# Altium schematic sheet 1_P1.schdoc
size 426 x 300 mm
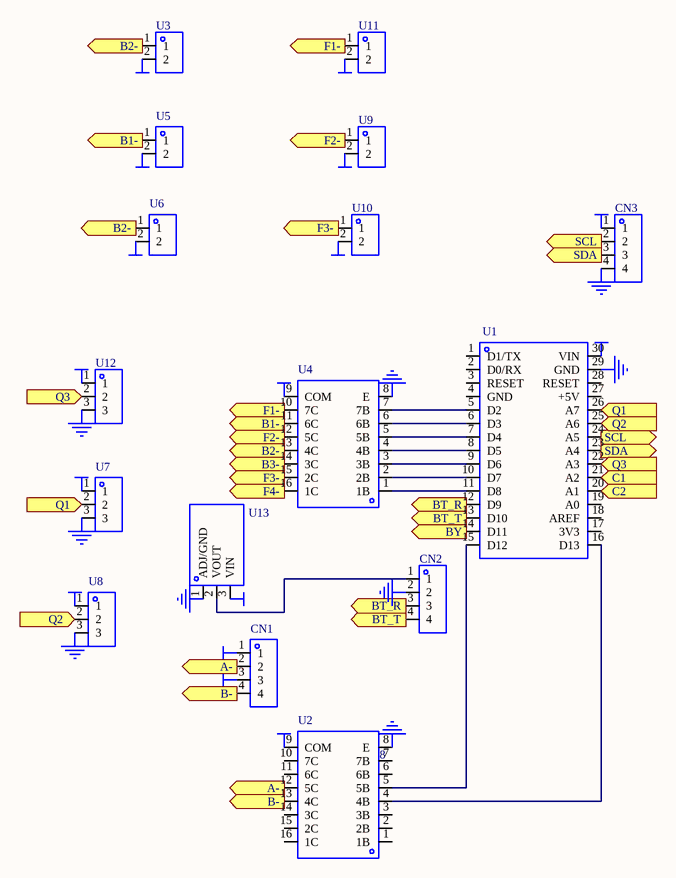
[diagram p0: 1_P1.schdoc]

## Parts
CN1  (no value)  [CONN-TH_XH-4A]
CN2  (no value)  [CONN-TH_XH-4A]
CN3  (no value)  [CONN-TH_XH-4A]
U1  (no value)  [COMM-TH_ARDUINO_NANO]
U2  NUMBER: 8  [SOIC-16_L9.9-W3.9-P1.27-LS6.0-BL]
U3  (no value)  [CONN-TH_2P-P2.50_XH-2A_3045048]
U4  (no value)  [SOIC-16_L9.9-W3.9-P1.27-LS6.0-BL]
U5  (no value)  [CONN-TH_2P-P2.50_XH-2A_3045048]
U6  (no value)  [CONN-TH_2P-P2.50_XH-2A_3045048]
U7  (no value)  [CONN-TH_XH-3A]
U8  (no value)  [CONN-TH_XH-3A]
U9  (no value)  [CONN-TH_2P-P2.50_XH-2A_3045048]
U10  (no value)  [CONN-TH_2P-P2.50_XH-2A_3045048]
U11  (no value)  [CONN-TH_2P-P2.50_XH-2A_3045048]
U12  (no value)  [CONN-TH_XH-3A]
U13  (no value)  [SOT-89-3_L4.5-W2.5-P1.50-LS4.2-BR]

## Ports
A- (out), B1- (out), B2- (out), B3- (out), B- (out), BT_R (out), BT_T (out), BY (out), C1 (in), C2 (in), F1- (out), F2- (out), F3- (out), F4- (out), Q1 (in), Q2 (in), Q3 (in), SCL (out), SDA (out)

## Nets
+5V: CN1.1 CN1.3 CN3.1 U1.30(VIN) U2.9(COM) U3.2 U4.9(COM) U5.2 U6.2 U7.1 U8.1 U9.2 U10.2 U11.2 U12.1 U13.3(VIN)
NetCN2_2: CN2.2 CN3.4 U1.29(GND) U2.8(E) U4.8(E) U7.3 U8.3 U12.3 U13.1(ADJ/GND)
A-: CN1.2 U2.12(5C) ; port A-
B1-: U4.11(6C) U5.1 ; port B1-
B2-: U3.1 U4.13(4C) U6.1 ; port B2-
B3-: U4.14(3C) ; port B3-
B-: CN1.4 U2.13(4C) ; port B-
BT_R: CN2.3 U1.12(D9) ; port BT_R
BT_T: CN2.4 U1.13(D10) ; port BT_T
BY: U1.14(D11) ; port BY
C1: U1.21(A2) ; port C1
C2: U1.20(A1) ; port C2
F1-: U4.10(7C) U11.1 ; port F1-
F2-: U4.12(5C) U9.1 ; port F2-
F3-: U4.15(2C) U10.1 ; port F3-
F4-: U4.16(1C) ; port F4-
Q1: U1.26(A7) U7.2 ; port Q1
Q2: U1.25(A6) U8.2 ; port Q2
Q3: U1.22(A3) U12.2 ; port Q3
SCL: CN3.2 U1.24(A5) ; port SCL
SDA: CN3.3 U1.23(A4) ; port SDA
NetCN2_1: CN2.1 U13.2(VOUT)
NetU1_5: U1.5(D2) U4.7(7B)
NetU1_6: U1.6(D3) U4.6(6B)
NetU1_7: U1.7(D4) U4.5(5B)
NetU1_8: U1.8(D5) U4.4(4B)
NetU1_9: U1.9(D6) U4.3(3B)
NetU1_10: U1.10(D7) U4.2(2B)
NetU1_11: U1.11(D8) U4.1(1B)
NetU1_15: U1.15(D12) U2.5(5B)
NetU1_16: U1.16(D13) U2.4(4B)

Not connected (* = marked no-connect by the designer): U1 1(D1/TX) 2(D0/RX) 3(RESET) 4(GND) 17(3V3) 18(AREF) 19(A0) 27(+5V) 28(RESET); U2 1(1B) 2(2B) 3(3B) 6(6B) 7(7B) 10(7C) 11(6C) 14(3C) 15(2C) 16(1C)

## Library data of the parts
CN1-CN3 = WAFER-XH254Z-4A: Manufacturer: HANBO(汉博); Add into BOM: yes; Pins Structure: 1x4P; Pitch: 2.54mm; Reference Series: XH; Number of PINs Per Row: 4; Current Rating (Max): 3A; Description: 插针结构:1x4P;间距:2.54mm;安装方式:直插;参考系列:XH;总PIN数:4P;排数:1;每排PIN数:4;额定电流:3A;工作温度范围:-25~+85;
U1 = ARDUINO_NANO: Add into BOM: yes
U2 U4 = ULN2003ADR: Manufacturer: TI(德州仪器); Add into BOM: yes; number of channels: 七路; Maximum collector Emitter Voltage (Vceo): 50V; Collector Current(Ic): 500mA; maximum input voltage: 30V; Description: 通道数:七路;集射击穿电压(Vceo):50V;集电极电流(Ic):500mA;
U3 U5 U6 U9-U11 = WAFER-XH254Z-2A: Manufacturer: HANBO(汉博); Add into BOM: yes; Pins Structure: 1x2P; Pitch: 2.54mm; Reference Series: XH; Number of PINs Per Row: 2; Current Rating (Max): 3A; Description: 插针结构:1x2P;间距:2.54mm;安装方式:直插;参考系列:XH;总PIN数:2P;排数:1;每排PIN数:2;额定电流:3A;工作温度范围:-25~+85;
U7 U8 U12 = WAFER-XH254Z-3A: Manufacturer: HANBO(汉博); Add into BOM: yes; Pins Structure: 1x3P; Pitch: 2.54mm; Reference Series: XH; Number of PINs Per Row: 3; Current Rating (Max): 3A; Description: 插针结构:1x3P;间距:2.54mm;安装方式:直插;参考系列:XH;总PIN数:3P;排数:1;每排PIN数:3;额定电流:3A;工作温度范围:-25~+85;
U13 = AMS1117-3.3_C880752: Manufacturer: Slkor(萨科微); Add into BOM: yes; Description: 输出类型:-;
